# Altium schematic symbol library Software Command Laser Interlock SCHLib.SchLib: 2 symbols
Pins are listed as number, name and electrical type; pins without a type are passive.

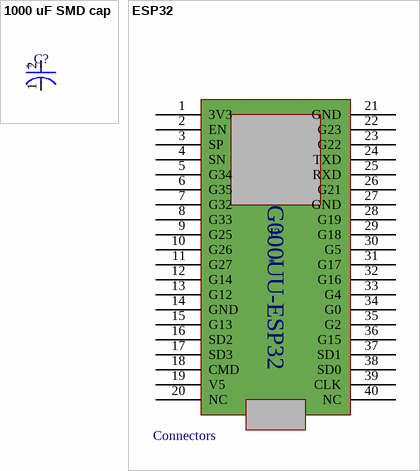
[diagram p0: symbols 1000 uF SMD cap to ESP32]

## 1000 uF SMD cap
designator C?
https://uk.farnell.com/kemet/t523h108m010ape070/cap-1000-f-10v-20/dp/2913804
footprint 1000 uF SMD Cap
pins: 1 C, 2 A

## ESP32
designator J?  Category: Connectors
2 x 1 row x 20 position header sockets to house the ESP32 DEV board
footprint ESP32 Footprint
3D model Model Name (PCB3D Model)
pins: 1 3V3, 2 EN, 3 SP, 4 SN, 5 G34, 6 G35, 7 G32, 8 G33, 9 G25, 10 G26, 11 G27, 12 G14, 13 G12, 14 GND, 15 G13, 16 SD2, 17 SD3, 18 CMD, 19 V5, 20 NC, 21 GND, 22 G23, 23 G22, 24 TXD, 25 RXD, 26 G21, 27 GND, 28 G19, 29 G18, 30 G5, 31 G17, 32 G16, 33 G4, 34 G0, 35 G2, 36 G15, 37 SD1, 38 SD0, 39 CLK, 40 NC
